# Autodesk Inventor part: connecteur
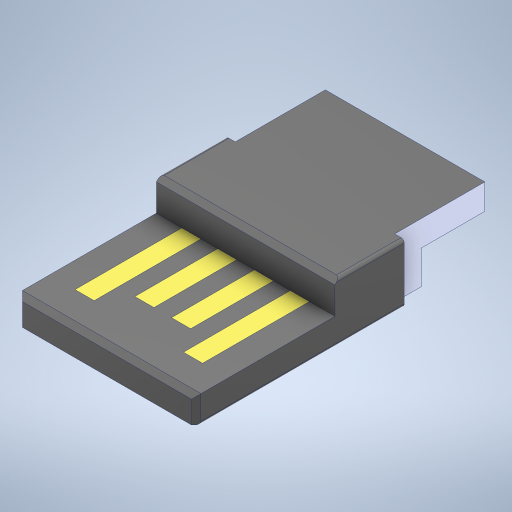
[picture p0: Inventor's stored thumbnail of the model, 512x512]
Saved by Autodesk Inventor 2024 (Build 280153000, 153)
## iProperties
Created: 2014-05
Part Number: connecteur
Material: Générique
Document SubType Name: Modeling
Designer: TVANDROUX
Density: 1 g/cm^3
Appearance: Par défaut
Sending System: SolidWorks 2010
Last Author: Jonathan
Last Saved: 2014-05-14
Author: TVANDROUX
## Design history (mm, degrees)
feature "Ligne de séparation1"
sketch "Esquisse1"
  geometry: L1 (0.4, 11.437)-(10.4, 11.437); L2 (10.4, 11.437)-(10.4, 4.049); L3 (10.4, 4.049)-(0.4, 4.049); L4 (0.4, 4.049)-(0.4, 11.437); L5 (10.4, 11.437)-(13.642, 11.437); L6 (13.642, 11.437)-(13.642, 4.049); L7 (13.642, 4.049)-(10.4, 4.049); L8 (10.4, 4.049)-(10.4, 11.437); L9 (0.4, 11.437)-(-2.314, 11.437); L10 (-2.314, 11.437)-(-2.314, 4.049); L11 (-2.314, 4.049)-(0.4, 4.049); L12 (0.4, 4.049)-(0.4, 11.437); L13 (11, 9.7)-(11, -0.2) reference; 3 further points
  constraints: 24 end point, 6 parallel, 3 horizontal, 3 perpendicular, 1 point on line
  dimensions: "d0" = 10 distance between parallel lines of L2 L4; "d1" = 0.6 distance between parallel lines of L2 L13
extrude "Extrusion1" cut sketch "Esquisse1" distance "d2" = 10; taper "d3" = 0 deg
node "Solide1"
